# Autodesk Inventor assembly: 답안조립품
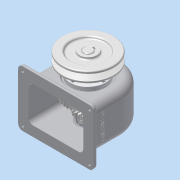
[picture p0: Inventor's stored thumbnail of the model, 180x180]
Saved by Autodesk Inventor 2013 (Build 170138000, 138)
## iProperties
Created: 2016-01
Part Number: 답안조립품
Document SubType Name: Assembly
Designer: Administrator
Author: Administrator
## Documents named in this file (16)
- C:\Users\Administrator\Desktop\460106V1036\답안조립품.iam
- C:\Users\Administrator\Desktop\460106V1036\답안도면.ipt
- C:\Users\Administrator\Desktop\460106V1036\뒤커버.ipt
- C:\Users\Administrator\Desktop\460106V1036\멈춤나사 - M4x10.ipt
- C:\Users\Administrator\Desktop\460106V1036\베어링 6203.ipt
- C:\Users\Administrator\Desktop\460106V1036\볼트 M3 x 8.ipt
- C:\Users\Administrator\Desktop\460106V1036\볼트 M3 x 10.ipt
- C:\Users\Administrator\Desktop\460106V1036\부시1.ipt
- C:\Users\Administrator\Desktop\460106V1036\부시2.ipt
- C:\Users\Administrator\Desktop\460106V1036\스퍼기어.ipt
- C:\Users\Administrator\Desktop\460106V1036\앞커버.ipt
- C:\Users\Administrator\Desktop\460106V1036\오일씰 28 40 8.ipt
- C:\Users\Administrator\Desktop\460106V1036\축.ipt
- C:\Users\Administrator\Desktop\460106V1036\키 - 5 x 5 x 18.ipt
- C:\Users\Administrator\Desktop\460106V1036\키 - 6 x 6 x 22.ipt
- C:\Users\Administrator\Desktop\460106V1036\V-벨트풀리.ipt
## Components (9 placed, 3 different names)
1. ISO 4762 M3 x 8:1
2. ISO 4762 M3 x 10:1
3. V-벨트풀리:1
4. ISO 4762 M3 x 8:2
5. ISO 4762 M3 x 8:3
6. ISO 4762 M3 x 8:4
7. ISO 4762 M3 x 10:2
8. ISO 4762 M3 x 10:3
9. ISO 4762 M3 x 10:4
